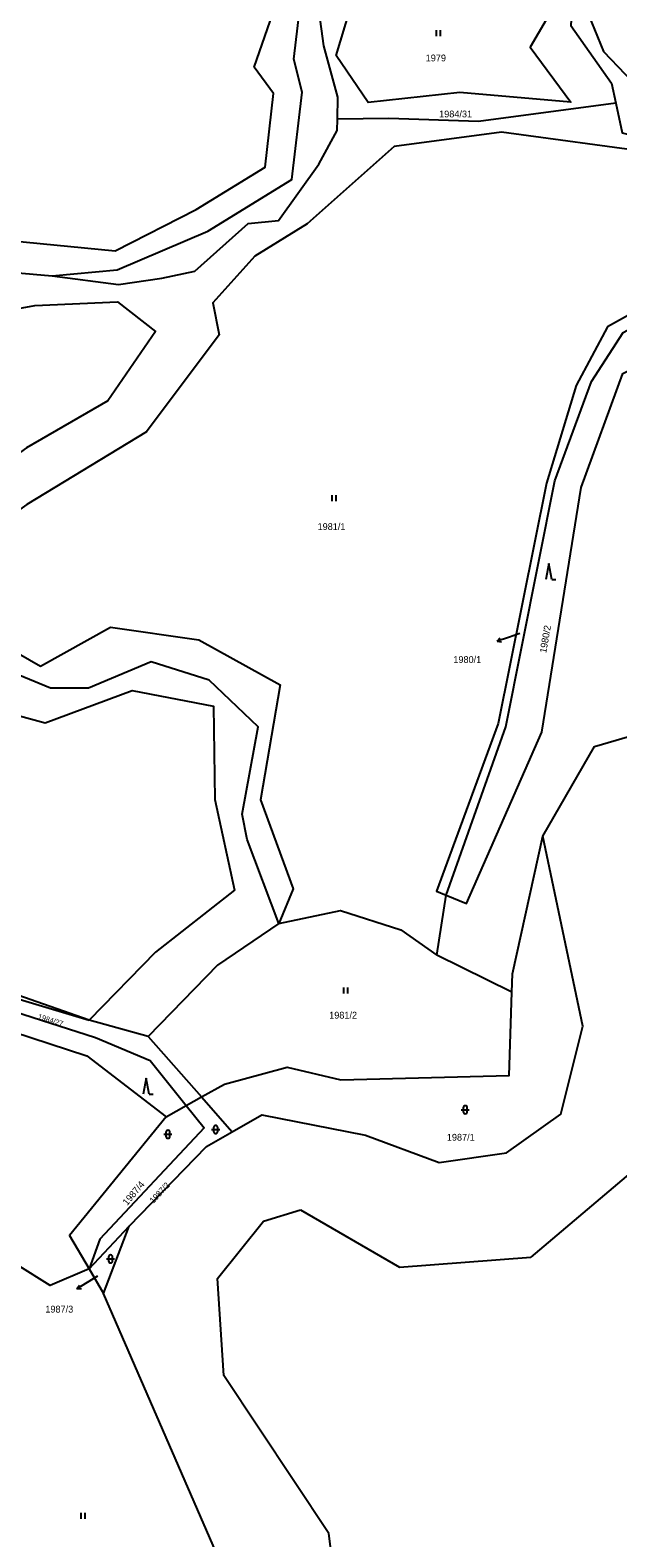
# Model space of a CAD drawing. Extents: x -504988 to -494607, y -1123820 to -1114018.
# Drawn here: x -495349.4 to -495202.8, y -1120297.2 to -1119921.1 of the extents above; entities that cross this region are included whole.
import ezdxf

# ---------------------------------------------------------------- set-up
doc = ezdxf.new("R2010")
doc.units = 0
for name, color, linetype in [('Hranice parcel', 7, 'Continuous'), ('Parcelní čísla', 7, 'Continuous'), ('Pop  PČ popisy', 7, 'Continuous'), ('Značky kultur', 7, 'Continuous')]:
    doc.layers.add(name, color=color, linetype=linetype)

msp = doc.modelspace()

# ---------------------------------------------------------------- linework, layer by layer
at = {"layer": 'Hranice parcel'}
for p, q in [((-495247.92, -1120151.9), (-495245.63, -1120136.9)), ((-495229.21, -1120161.11), (-495247.92, -1120151.9)), ((-495319.96, -1120172.13), (-495334.73, -1120168.06)), ((-495319.96, -1120172.13), (-495306.63, -1120187.26)), ((-495315.46, -1120192.21), (-495310.47, -1120189.42)), ((-495310.47, -1120189.42), (-495306.63, -1120187.26)), ((-495306.63, -1120187.26), (-495299, -1120195.92)), ((-495193.35, -1120200.84), (-495224.49, -1120227.2)), ((-495334.65, -1120230.09), (-495324.67, -1120219.48)), ((-495331.08, -1120236.26), (-495324.67, -1120219.48)), ((-495334.65, -1120230.09), (-495331.08, -1120236.26)), ((-495274.91, -1120296.19), (-495301.09, -1120256.7))]:
    msp.add_line(p, q, dxfattribs=at)
for points in [[(-495343.9, -1119982.42), (-495327.68, -1119980.92), (-495305.05, -1119971.25), (-495284.16, -1119958.36), (-495281.55, -1119936.61), (-495283.64, -1119928.39), (-495282.25, -1119916.47), (-495266.93, -1119905.19), (-495235.95, -1119899.71), (-495223.96, -1119904.34), (-495211.58, -1119913.57), (-495206.36, -1119926.46), (-495195.57, -1119937.74), (-495184.33, -1119935.55), (-495179.54, -1119892.19), (-495210.88, -1119877.47), (-495246.96, -1119865.26), (-495265, -1119857.06), (-495271.11, -1119851.05), (-495278.84, -1119839.39)], [(-495272.75, -1119943.29), (-495272.68, -1119937.83), (-495276.13, -1119925.03), (-495277.32, -1119916.53), (-495266.41, -1119909.33), (-495244.79, -1119904.52), (-495235.61, -1119903.12), (-495214.21, -1119914.33), (-495214.54, -1119919.93), (-495204.38, -1119934.33), (-495203.28, -1119939.37)], [(-495386.3, -1119984.03), (-495372.37, -1119972.07), (-495354.58, -1119973.59), (-495328.24, -1119976.17), (-495307.99, -1119965.84), (-495290.76, -1119955.27), (-495288.71, -1119936.93), (-495293.55, -1119930.34), (-495284.83, -1119905.17)], [(-495233.24, -1119907.06), (-495218.65, -1119915.17), (-495224.66, -1119925.37), (-495214.54, -1119939.08), (-495242.21, -1119936.71), (-495265.05, -1119939.19), (-495273.1, -1119927.4), (-495269.59, -1119915.89), (-495254.06, -1119910.2), (-495233.24, -1119907.06)], [(-495203.28, -1119939.37), (-495237.52, -1119943.87), (-495259.91, -1119943.17), (-495272.75, -1119943.29)], [(-495203.28, -1119939.37), (-495201.68, -1119946.74), (-495193.89, -1119948.74), (-495183.78, -1119942.96)], [(-495343.9, -1119982.42), (-495327.36, -1119984.55), (-495316.55, -1119982.95), (-495308.34, -1119981.25), (-495295.05, -1119969.34), (-495287.48, -1119968.64), (-495277.43, -1119954.54), (-495272.78, -1119946.14), (-495272.75, -1119943.29)], [(-495162.77, -1119953.78), (-495186.59, -1119947.96), (-495193.84, -1119951.74), (-495231.79, -1119946.58), (-495258.58, -1119950.15), (-495280.33, -1119969.42), (-495293.34, -1119977.49), (-495303.87, -1119989.13), (-495302.22, -1119997.12), (-495320.38, -1120021.3), (-495350.27, -1120039.48), (-495372.78, -1120055.43), (-495364.34, -1120069.68), (-495346.81, -1120079.75), (-495329.38, -1120070.03), (-495307.36, -1120073.23), (-495287.01, -1120084.4), (-495291.95, -1120113.15), (-495283.79, -1120135.36), (-495287.39, -1120143.94)], [(-495370.52, -1119984.7), (-495360.11, -1119981.02), (-495343.9, -1119982.42)], [(-495350.35, -1120025.34), (-495370.64, -1120039.84), (-495381.61, -1120057.52), (-495404.4, -1120043.9), (-495395.1, -1120029.1), (-495384.25, -1120033.46), (-495367.62, -1120020.5), (-495368.31, -1120006.81), (-495365.94, -1119993.07), (-495348.23, -1119989.83), (-495327.58, -1119988.87), (-495318.11, -1119996.29), (-495330.07, -1120013.58), (-495350.35, -1120025.34)], [(-495192.69, -1119988.04), (-495205.36, -1119995.09), (-495213.17, -1120009.76), (-495220.61, -1120034.11), (-495232.66, -1120094.06), (-495248.02, -1120135.93), (-495245.63, -1120136.9)], [(-495245.63, -1120136.9), (-495230.78, -1120094.91), (-495218.51, -1120033.51), (-495209.35, -1120008.79), (-495201.49, -1119996.53), (-495191.85, -1119991.36)], [(-495245.63, -1120136.9), (-495240.52, -1120138.96), (-495221.78, -1120096.27), (-495211.93, -1120035.18), (-495201.51, -1120006.77), (-495189.47, -1120000.77)], [(-495221.51, -1120122.19), (-495208.59, -1120099.85), (-495152.35, -1120083.38), (-495129.87, -1120062.04), (-495138.82, -1120039.08), (-495155.95, -1120033.87), (-495172.26, -1120021.34), (-495189.47, -1120000.77)], [(-495287.39, -1120143.94), (-495295.27, -1120122.99), (-495296.5, -1120116.74), (-495292.51, -1120094.89), (-495304.78, -1120083.26), (-495319.19, -1120078.71), (-495334.83, -1120085.24), (-495344.33, -1120085.24), (-495365.8, -1120076.44), (-495380.52, -1120065.38), (-495407.81, -1120049.73)], [(-495469.2, -1120120.16), (-495457.93, -1120092.03), (-495444.76, -1120073.43), (-495423.14, -1120055.86), (-495411.96, -1120055.62), (-495386.72, -1120072.88), (-495362.19, -1120089.4), (-495345.7, -1120093.92), (-495323.95, -1120085.87), (-495303.66, -1120089.8), (-495303.35, -1120113.02), (-495298.43, -1120135.68), (-495318.1, -1120151.11), (-495334.73, -1120168.06)], [(-495334.73, -1120168.06), (-495415.95, -1120139.67), (-495434.36, -1120121), (-495452.82, -1120122.82), (-495469.2, -1120120.16)], [(-495299, -1120195.92), (-495291.61, -1120191.73), (-495265.74, -1120196.81), (-495247.41, -1120203.6), (-495230.56, -1120201.2), (-495217.03, -1120191.56), (-495211.49, -1120169.63), (-495221.51, -1120122.19)], [(-495229.21, -1120161.11), (-495229.06, -1120156.54), (-495221.51, -1120122.19)], [(-495287.39, -1120143.94), (-495271.98, -1120140.74), (-495256.94, -1120145.57), (-495247.92, -1120151.9)], [(-495287.39, -1120143.94), (-495302.65, -1120154.38), (-495319.96, -1120172.13)], [(-495403.13, -1120149.94), (-495402.42, -1120147.79), (-495334.73, -1120168.06)], [(-495403.13, -1120149.94), (-495333.1, -1120172.43), (-495319.5, -1120178.17), (-495310.47, -1120189.42)], [(-495404.17, -1120154.47), (-495335.25, -1120176.97), (-495315.46, -1120192.21)], [(-495306.63, -1120187.26), (-495300.96, -1120184.09), (-495285.28, -1120179.85), (-495271.9, -1120182.97), (-495229.9, -1120181.93), (-495229.21, -1120161.11)], [(-495310.47, -1120189.42), (-495306.04, -1120194.93), (-495332.06, -1120222.69), (-495334.65, -1120230.09)], [(-495315.46, -1120192.21), (-495339.63, -1120221.85), (-495334.65, -1120230.09)], [(-495324.67, -1120219.48), (-495305.45, -1120199.58), (-495299, -1120195.92)], [(-495301.09, -1120256.7), (-495302.7, -1120232.53), (-495291.17, -1120218.22), (-495281.97, -1120215.41)], [(-495281.97, -1120215.41), (-495257.3, -1120229.7), (-495224.49, -1120227.2)], [(-495334.65, -1120230.09), (-495344.45, -1120234.26), (-495352.69, -1120229.17)], [(-495430.85, -1120330.53), (-495411.78, -1120345.58), (-495304.88, -1120320.87), (-495300.71, -1120306.2), (-495331.08, -1120236.26)], [(-495283.95, -1120340.01), (-495272.08, -1120318.69), (-495274.91, -1120296.19)]]:
    msp.add_lwpolyline(points, dxfattribs=at)
at = {"layer": 'Pop  PČ popisy'}
for p, q in [((-495230.06, -1120072.59), (-495232.91, -1120073.52)), ((-495232.91, -1120073.52), (-495232.12, -1120072.73)), ((-495227.21, -1120071.67), (-495230.06, -1120072.59)), ((-495232.91, -1120073.52), (-495231.81, -1120073.68)), ((-495335.18, -1120233.56), (-495337.73, -1120235.15)), ((-495337.73, -1120235.15), (-495337.14, -1120234.2)), ((-495332.63, -1120232), (-495335.18, -1120233.56)), ((-495337.73, -1120235.15), (-495336.61, -1120235.04))]:
    msp.add_line(p, q, dxfattribs=at)
at = {"layer": 'Značky kultur'}
for p, q in [((-495248.07, -1119922.65), (-495248.07, -1119921.15)), ((-495247.07, -1119922.65), (-495247.07, -1119921.15)), ((-495274.07, -1120038.65), (-495274.07, -1120037.15)), ((-495273.07, -1120038.65), (-495273.07, -1120037.15)), ((-495220, -1120054.2), (-495220.75, -1120058.2)), ((-495219.25, -1120058.2), (-495220, -1120054.2)), ((-495219.25, -1120058.2), (-495218.25, -1120058.2)), ((-495271.17, -1120161.45), (-495271.17, -1120159.95)), ((-495270.17, -1120161.45), (-495270.17, -1120159.95)), ((-495320.5, -1120182.57), (-495321.25, -1120186.57)), ((-495319.75, -1120186.57), (-495320.5, -1120182.57)), ((-495319.75, -1120186.57), (-495318.75, -1120186.57)), ((-495241.85, -1120190.44), (-495239.85, -1120190.44)), ((-495241.35, -1120189.94), (-495241.35, -1120190.94)), ((-495240.35, -1120190.94), (-495240.35, -1120189.94)), ((-495316.03, -1120196.57), (-495314.03, -1120196.57)), ((-495315.53, -1120196.07), (-495315.53, -1120197.07)), ((-495314.53, -1120197.07), (-495314.53, -1120196.07)), ((-495304.13, -1120195.37), (-495302.13, -1120195.37)), ((-495303.63, -1120194.87), (-495303.63, -1120195.87)), ((-495302.63, -1120195.87), (-495302.63, -1120194.87)), ((-495329.85, -1120227.17), (-495329.85, -1120228.17)), ((-495328.85, -1120228.17), (-495328.85, -1120227.17)), ((-495330.35, -1120227.67), (-495328.35, -1120227.67)), ((-495336.67, -1120292.53), (-495336.67, -1120291.03)), ((-495335.67, -1120292.53), (-495335.67, -1120291.03))]:
    msp.add_line(p, q, dxfattribs=at)
for centre, start, end in [((-495240.85, -1120189.94), 0, 180), ((-495240.85, -1120190.94), 180, 359.9879), ((-495315.03, -1120196.07), 0, 180), ((-495315.03, -1120197.07), 180, 359.9879), ((-495303.13, -1120194.87), 0, 180), ((-495303.13, -1120195.87), 180, 359.9879), ((-495329.35, -1120227.17), 0, 180), ((-495329.35, -1120228.17), 180, 359.9879)]:
    msp.add_arc(centre, 0.5, start, end, dxfattribs=at)

# ---------------------------------------------------------------- texts
at = {"layer": 'Parcelní čísla'}
for s, p in [('1979', (-495250.73, -1119928.9)), ('1984/31', (-495247.38, -1119942.88)), ('1981/1', (-495277.71, -1120045.81)), ('1980/1', (-495243.83, -1120078.98)), ('1981/2', (-495274.81, -1120167.7)), ('1987/1', (-495245.46, -1120198.16)), ('1987/3', (-495345.62, -1120241.04))]:
    msp.add_text(s, height=1.7, dxfattribs=at).set_placement(p)
for s, height, rotation, p in [('1980/2', 1.7, 80, (-495220.67, -1120076.6)), ('1984/27', 1.3, 343, (-495347.58, -1120167.74)), ('1987/4', 1.7, 50, (-495325.2, -1120214.47)), ('1987/2', 1.5, 47, (-495318.65, -1120213.9))]:
    msp.add_text(s, height=height, rotation=rotation, dxfattribs=at).set_placement(p)

doc.saveas('drawing.dxf')
